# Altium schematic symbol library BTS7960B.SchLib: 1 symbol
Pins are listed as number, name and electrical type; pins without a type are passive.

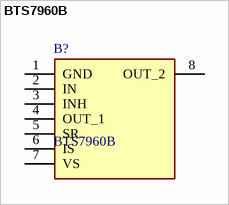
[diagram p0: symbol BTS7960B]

## BTS7960B
designator B?
Path resistance of typ. 16 m @ 25 C; Manufacturer_Name: Rochester Electronics; Geometry.Height: 4.4mm
footprint BTS7960B
pins: 1 GND, 2 IN, 3 INH, 4 OUT_1, 5 SR, 6 IS, 7 VS, 8 OUT_2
